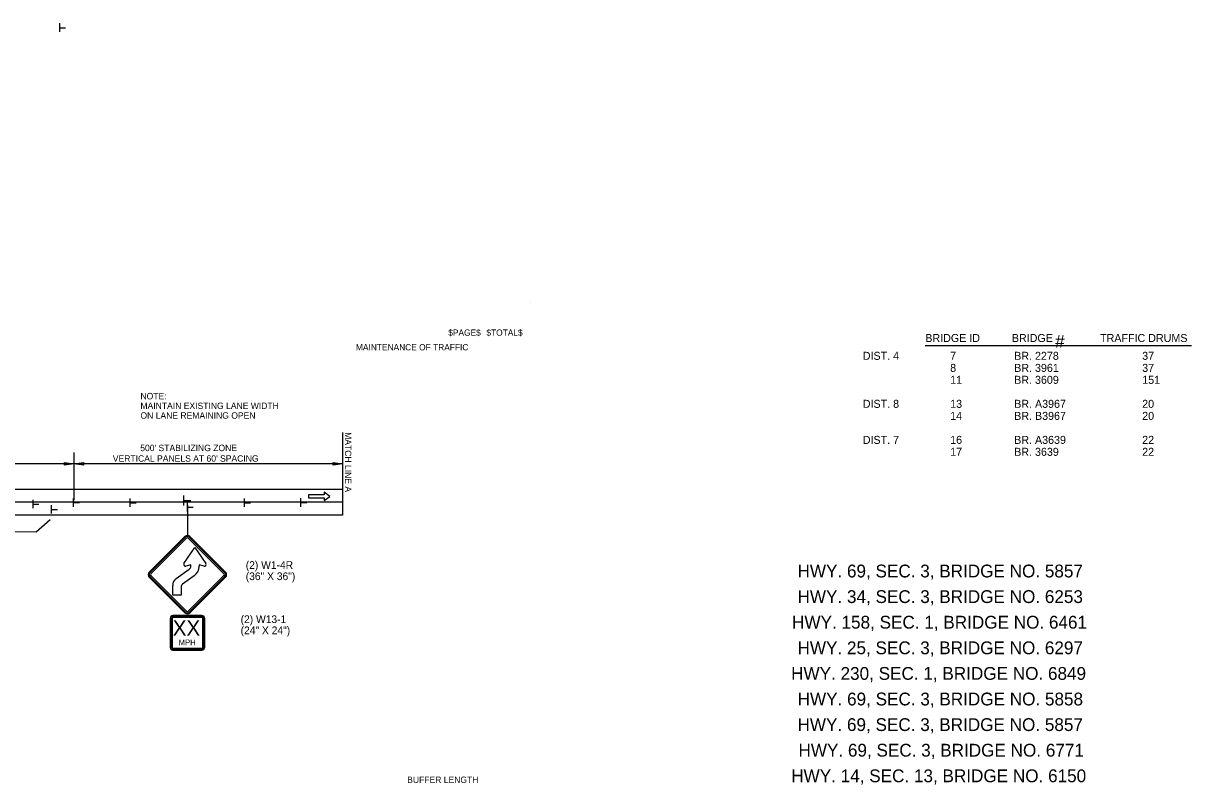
# Model space of a CAD drawing. Extents: x 1930579 to 1937521, y 596183 to 597599.
# Drawn here: x 1936204 to 1937299, y 596886 to 597599 of the extents above; entities that cross this region are included whole.
import ezdxf

# ---------------------------------------------------------------- set-up
doc = ezdxf.new("R2010")
doc.units = 0
for name, color, linetype in [('Default', 7, 'Continuous'), ('P_TC_Signs_Permanent', 7, 'Continuous'), ('R_Annotation', 7, 'Continuous'), ('R_Border', 7, 'Continuous'), ('R_Striping', 7, 'Continuous')]:
    doc.layers.add(name, color=color, linetype=linetype)

msp = doc.modelspace()

# ---------------------------------------------------------------- linework, layer by layer
at = {"layer": 'Default'}
for p, q in [((1936237.9, 597591.5), (1936237.9, 597599.5)), ((1936238, 597595.4), (1936243.5, 597595.4)), ((1936503, 597215.8), (1936503, 597138.5)), ((1936251.3, 597197), (1936251.3, 597152.4)), ((1936251.3, 597186.5), (1935884.1, 597186.5)), ((1936242.4, 597185.2), (1936242.4, 597187.8)), ((1936242.4, 597187.8), (1936251.3, 597186.5)), ((1936251.3, 597186.5), (1936242.4, 597185.2)), ((1936251.3, 597186.5), (1936260.2, 597187.8)), ((1936503, 597186.5), (1936251.3, 597186.5)), ((1936260.2, 597185.2), (1936251.3, 597186.5)), ((1936260.2, 597187.8), (1936260.2, 597185.2)), ((1936494.2, 597185.2), (1936494.2, 597187.8)), ((1936494.2, 597187.8), (1936503, 597186.5)), ((1936503, 597186.5), (1936494.2, 597185.2)), ((1936503, 597162.5), (1935188.5, 597162.5)), ((1936503, 597150.5), (1935188.5, 597150.5)), ((1936213, 597144.9), (1936213, 597152.8)), ((1936213.1, 597148.8), (1936218.5, 597148.8)), ((1936250.9, 597146.1), (1936250.9, 597154.1)), ((1936251, 597150.1), (1936256.5, 597150.1)), ((1936304.1, 597146.1), (1936304.1, 597154.1)), ((1936304.2, 597150), (1936309.7, 597150)), ((1936354.2, 597147.3), (1936354.2, 597156.8)), ((1936354.3, 597152), (1936360.9, 597152)), ((1936357.6, 597141.8), (1936357.6, 597149.8)), ((1936411, 597146.1), (1936411, 597154.1)), ((1936411.2, 597150), (1936416.6, 597150)), ((1936463.9, 597146.3), (1936463.9, 597154.3)), ((1936464.1, 597150.3), (1936469.5, 597150.3)), ((1936503, 597138.5), (1935188.5, 597138.5)), ((1936230.3, 597139.9), (1936230.3, 597147.9)), ((1936230.4, 597143.8), (1936235.9, 597143.8)), ((1936357.7, 597145.8), (1936363.1, 597145.8))]:
    msp.add_line(p, q, dxfattribs=at)
at = {"layer": 'P_TC_Signs_Permanent'}
for p, q in [((1936321.8, 597085), (1936355.2, 597118.4)), ((1936322.4, 597084.4), (1936355.9, 597117.8)), ((1936356.8, 597116.8), (1936323.4, 597083.4)), ((1936391.8, 597083.4), (1936358.4, 597116.8)), ((1936359.4, 597117.8), (1936392.8, 597084.4)), ((1936360, 597118.4), (1936393.4, 597085)), ((1936347.1, 597078.9), (1936359.4, 597087.8)), ((1936355.2, 597046.8), (1936321.8, 597080.2)), ((1936355.9, 597047.5), (1936322.4, 597080.9)), ((1936323.4, 597081.8), (1936356.8, 597048.4)), ((1936364, 597081.4), (1936353.1, 597073.6)), ((1936358.4, 597048.4), (1936391.8, 597081.8)), ((1936392.8, 597080.9), (1936359.4, 597047.5)), ((1936393.4, 597080.2), (1936360, 597046.8)), ((1936341.4, 597041.6), (1936341.4, 597014.6)), ((1936342.1, 597041.6), (1936342.1, 597014.6)), ((1936343.2, 597041.6), (1936343.2, 597014.6)), ((1936371.1, 597044.3), (1936344.1, 597044.3)), ((1936371.1, 597043.6), (1936344.1, 597043.6)), ((1936371.1, 597042.5), (1936344.1, 597042.5)), ((1936372, 597014.6), (1936372, 597041.6)), ((1936373.1, 597014.6), (1936373.1, 597041.6)), ((1936373.8, 597014.6), (1936373.8, 597041.6)), ((1936344.1, 597013.7), (1936371.1, 597013.7)), ((1936344.1, 597012.5), (1936371.1, 597012.5)), ((1936344.1, 597011.9), (1936371.1, 597011.9))]:
    msp.add_line(p, q, dxfattribs=at)
for points in [[(1936354.4, 597092.9), (1936364.7, 597107.9), (1936375, 597092.9)], [(1936360.8, 597090.5), (1936360.8, 597091.9), (1936356.2, 597090.5)], [(1936373.2, 597090.5), (1936368.6, 597091.9), (1936368.6, 597090.5)], [(1936351.7, 597070.8), (1936351.7, 597063.5), (1936343.8, 597063.5), (1936343.8, 597072.5)]]:
    msp.add_lwpolyline(points, dxfattribs=at)
for centre, radius, start, end in [((1936357.6, 597116), 3.38, 45, 135), ((1936357.6, 597116), 2.47, 45, 135), ((1936357.6, 597116), 1.12, 45, 135), ((1936324.2, 597082.6), 3.37, 135, 225), ((1936324.2, 597082.6), 2.47, 135, 225), ((1936324.2, 597082.6), 1.12, 135, 225), ((1936355.7, 597092), 1.57, 145.6763, 287.8128), ((1936357.4, 597090.5), 3.38, 305.7733, 0), ((1936357.4, 597090.5), 11.2, 305.7733, 0), ((1936373.7, 597092), 1.57, 252.1872, 34.3237), ((1936391, 597082.6), 1.12, 315, 45), ((1936391, 597082.6), 2.47, 315, 45), ((1936391, 597082.6), 3.37, 315, 45), ((1936351.7, 597072.5), 7.87, 125.7733, 180), ((1936355.1, 597070.8), 3.38, 125.7733, 180), ((1936344.1, 597041.6), 2.7, 90, 180), ((1936344.1, 597041.6), 2.03, 90, 180), ((1936344.1, 597041.6), 0.9, 90, 180), ((1936357.6, 597049.2), 3.37, 225, 315), ((1936357.6, 597049.2), 2.47, 225, 315), ((1936357.6, 597049.2), 1.12, 225, 315), ((1936371.1, 597041.6), 2.7, 360, 90), ((1936371.1, 597041.6), 2.03, 360, 90), ((1936371.1, 597041.6), 0.9, 360, 90), ((1936344.1, 597014.6), 2.7, 180, 270), ((1936344.1, 597014.6), 2.03, 180, 270), ((1936344.1, 597014.6), 0.9, 180, 270), ((1936371.1, 597014.6), 2.7, 270, 360), ((1936371.1, 597014.6), 2.03, 270, 360), ((1936371.1, 597014.6), 0.9, 270, 360)]:
    msp.add_arc(centre, radius, start, end, dxfattribs=at)
at = {"layer": 'R_Annotation'}
for p, q in [((1937049.3, 597297.3), (1937298.9, 597297.3)), ((1936357.6, 597147.8), (1936357.6, 597119.4))]:
    msp.add_line(p, q, dxfattribs=at)
msp.add_lwpolyline([(1936008.1, 597131), (1936019.9, 597124), (1936099.1, 597124), (1936099.8, 597115.7), (1936102.6, 597123.3), (1936215.8, 597122.6), (1936229, 597134.4)], dxfattribs=at)
at = {"layer": 'R_Border'}
msp.add_line((1936679.4, 597337.3), (1936679.4, 597337.3), dxfattribs=at)
at = {"layer": 'R_Striping'}
msp.add_lwpolyline([(1936485.8, 597152), (1936491, 597156), (1936485.8, 597160), (1936485.8, 597157.5), (1936471.1, 597157.5), (1936471.1, 597154.5), (1936485.8, 597154.5)], close=True, dxfattribs=at)

# ---------------------------------------------------------------- texts
at = {"layer": 'Default'}
for s, height, rotation, p in [('MATCH LINE A', 6, 270, (1936505.3, 597216.2)), ("500' STABILIZING ZONE", 6, 360, (1936313.4, 597198.4)), ("VERTICAL PANELS AT 60' SPACING", 6, 360, (1936287.7, 597188.5)), ('HWY. 69, SEC. 3, BRIDGE NO. 5857', 12, 360, (1936929.5, 597080)), ('HWY. 34, SEC. 3, BRIDGE NO. 6253', 12, 360, (1936929.5, 597056)), ('HWY. 158, SEC. 1, BRIDGE NO. 6461', 12, 360, (1936924.4, 597032)), ('HWY. 25, SEC. 3, BRIDGE NO. 6297', 12, 360, (1936929.5, 597008)), ('HWY. 230, SEC. 1, BRIDGE NO. 6849', 12, 360, (1936923.5, 596984)), ('HWY. 69, SEC. 3, BRIDGE NO. 5858', 12, 360, (1936929.6, 596960)), ('HWY. 69, SEC. 3, BRIDGE NO. 5857', 12, 360, (1936929.5, 596936)), ('HWY. 69, SEC. 3, BRIDGE NO. 6771', 12, 360, (1936930.4, 596912)), ('HWY. 14, SEC. 13, BRIDGE NO. 6150', 12, 360, (1936923.6, 596888))]:
    msp.add_text(s, height=height, rotation=rotation, dxfattribs=at).set_placement(p)
at = {"layer": 'P_TC_Signs_Permanent'}
for s, height, p in [('XX', 14.4, (1936343.9, 597025.4)), ('MPH', 5.4, (1936349.4, 597016.4))]:
    msp.add_text(s, height=height, rotation=360, dxfattribs=at).set_placement(p)
at = {"layer": 'R_Annotation'}
for s, height, p in [('BRIDGE ID', 7.5, (1937049.3, 597300.7)), ('BRIDGE ', 7.5, (1937130.4, 597300.7)), ('#', 12, (1937171, 597295.4)), ('TRAFFIC DRUMS', 7.5, (1937213.1, 597300.7)), ('DIST. 4', 7.5, (1936990.7, 597284)), ('7', 7.5, (1937072.6, 597284)), ('BR. 2278', 7.5, (1937132.6, 597284)), ('37', 7.5, (1937252.6, 597284)), ('8', 7.5, (1937072.6, 597272.7)), ('BR. 3961', 7.5, (1937132.6, 597272.7)), ('37', 7.5, (1937252.6, 597272.7)), ('BR. 3609', 7.5, (1937132.6, 597261.5)), ('11', 7.5, (1937072.6, 597261.5)), ('151', 7.5, (1937252.6, 597261.5)), ('NOTE:', 6, (1936313.6, 597247)), ('MAINTAIN EXISTING LANE WIDTH', 6, (1936313.6, 597237.9)), ('DIST. 8', 7.5, (1936990.7, 597239)), ('13', 7.5, (1937072.6, 597239)), ('BR. A3967', 7.5, (1937132.6, 597239)), ('20', 7.5, (1937252.6, 597239)), ('ON LANE REMAINING OPEN', 6, (1936313.6, 597228.8)), ('14', 7.5, (1937072.6, 597227.7)), ('BR. B3967', 7.5, (1937132.6, 597227.7)), ('20', 7.5, (1937252.6, 597227.7)), ('DIST. 7', 7.5, (1936990.7, 597205.2)), ('16', 7.5, (1937072.6, 597205.2)), ('BR. A3639', 7.5, (1937132.6, 597205.2)), ('22', 7.5, (1937252.6, 597205.2)), ('17', 7.5, (1937072.6, 597194)), ('BR. 3639', 7.5, (1937132.6, 597194)), ('22', 7.5, (1937252.6, 597194)), ('(2) W1-4R', 7.2, (1936412.3, 597088)), ('(36" X 36")', 7.2, (1936412.3, 597077.5)), ('(2) W13-1', 7.2, (1936407.5, 597037.2)), ('(24" X 24")', 7.2, (1936407.5, 597026.8)), ('BUFFER LENGTH', 6, (1936563.6, 596887.3))]:
    msp.add_text(s, height=height, rotation=360, dxfattribs=at).set_placement(p)
at = {"layer": 'R_Border'}
for s, height, p in [('$PAGE$', 5.86, (1936602.1, 597306.6)), ('$TOTAL$', 5.86, (1936637.9, 597306.6)), ('MAINTENANCE OF TRAFFIC', 5.862, (1936515.6, 597292.9)), ('MAINTENANCE OF TRAFFIC', 5.862, (1936515.6, 597292.9))]:
    msp.add_text(s, height=height, rotation=360, dxfattribs=at).set_placement(p)

doc.saveas('drawing.dxf')
